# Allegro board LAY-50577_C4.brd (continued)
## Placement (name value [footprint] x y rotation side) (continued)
NOREF#382  -  []  43.78 72.53 90 top
NOREF#383  -  []  133.83 41.2 0 top
NOREF#384  -  []  25.45 88.8 0 top
NOREF#385  -  []  83.29 7.45 90 top
NOREF#386  -  []  130.23 108.22 90 top
NOREF#387  -  []  110.98 104.71 90 top
NOREF#388  -  []  83.87 128.98 90 top
NOREF#389  -  []  106.8 104.59 90 top
NOREF#390  -  []  103.8 117.48 0 top
NOREF#391  -  []  107.3 28.4 0 top
NOREF#392  -  []  17.47 6.14 0 top
NOREF#393  -  []  151.28 118.2 90 top
NOREF#394  -  []  44.06 79.82 0 top
NOREF#395  -  []  73.37 129.71 0 top
NOREF#396  -  []  60.01 28.57 0 top
NOREF#397  -  []  43.57 6.99 90 top
NOREF#398  -  []  132.14 116.34 90 top
NOREF#399  -  []  94.12 136.35 0 top
NOREF#400  -  []  44.06 83.51 0 top
NOREF#401  -  []  184.84 57.38 0 top
NOREF#402  -  []  42.13 84.28 0 top
NOREF#403  -  []  69.83 10.49 0 top
NOREF#404  -  []  101.03 70.84 0 top
NOREF#405  -  []  136.07 94.51 90 top
NOREF#406  -  []  27.95 62.56 0 top
NOREF#407  -  []  0.36 129.9 0 top
NOREF#408  -  []  42.13 80.6 0 top
NOREF#409  -  []  104.95 117.48 90 top
NOREF#410  -  []  44.06 76.14 0 top
NOREF#411  -  []  111.68 105.37 90 top
NOREF#412  -  []  24.27 60.15 0 top
NOREF#413  -  []  6.73 13.77 90 top
NOREF#414  -  []  149.85 122.51 90 top
NOREF#415  -  []  39.15 113.38 90 top
NOREF#416  -  []  145.53 122.78 90 top
NOREF#417  -  []  123.1 24.13 0 top
NOREF#418  -  []  102.89 68.87 0 top
NOREF#419  -  []  10.89 99.12 0 top
NOREF#420  -  []  32.65 88.09 0 top
NOREF#421  -  []  82.02 16.34 0 top
NOREF#422  -  []  165.05 112.24 90 top
NOREF#423  -  []  191.46 87.67 90 top
NOREF#424  -  []  139.21 122.2 90 top
NOREF#425  -  []  102.08 71.17 90 top
NOREF#426  -  []  17.25 135.97 0 top
NOREF#427  -  []  167.23 36.07 0 top
NOREF#428  -  []  108.58 45.09 90 top
NOREF#429  -  []  42.78 73.94 0 top
NOREF#430  -  []  118.26 90.02 0 top
NOREF#431  -  []  155.96 123.13 90 top
NOREF#432  -  []  170.76 96.92 0 top
NOREF#433  -  []  30.3 1.64 90 top
NOREF#434  -  []  27.7 57.74 0 top
NOREF#435  -  []  6.47 119.99 90 top
NOREF#436  -  []  85.14 122.69 90 top
NOREF#437  -  [unnamed#2]  191.07 9.43 0 top
NOREF#438  -  []  10.89 99.12 90 top
NOREF#439  -  []  95.92 58.1 90 top
NOREF#440  -  []  185.48 56.28 0 top
NOREF#441  -  []  154.54 73.43 0 top
NOREF#442  -  []  151.23 122.78 90 top
NOREF#443  -  []  59.2 84.28 0 top
NOREF#444  -  []  50.27 13.8 90 top
NOREF#445  -  []  162.03 59.26 0 top
NOREF#446  -  []  70.12 136.35 0 top
NOREF#447  -  []  145.64 72.02 90 top
NOREF#448  -  []  50.63 3.37 0 top
NOREF#449  -  []  42.13 65.86 0 top
NOREF#450  -  []  91.76 28.57 90 top
NOREF#451  -  []  15.89 107.65 0 top
NOREF#452  -  []  110.2 104.59 0 top
NOREF#453  -  []  101.12 71.46 90 top
NOREF#454  -  []  32.31 82.43 90 top
NOREF#455  -  []  134.92 94.51 0 top
NOREF#456  -  []  119.37 135.23 90 top
NOREF#457  -  []  154.3 123.95 0 top
NOREF#458  -  []  43.78 83.57 90 top
NOREF#459  -  []  100.93 71.17 0 top
NOREF#460  -  [unnamed#2]  3.41 130.95 180 bottom
NOREF#461  -  [unnamed#2]  9.12 4.65 180 bottom
NOREF#462  -  []  186.67 67.13 180 bottom
NOREF#463  -  [unnamed#2]  191.07 9.43 180 bottom
NOREF#464  -  [unnamed#2]  185.1 136.16 180 bottom
NOREF#465  -  []  186.67 60.02 180 bottom
NOREF#466  -  []  105.64 1.09 180 bottom
NOREF#467  -  []  168.76 25.61 180 bottom
P2  POM-2244P-C3310-2-R  [MIC_WM-63PR]  98.53 121.24 0 top
Q1  FDMA530PZ  [MLP6_2X2MM_SLUG]  25.76 12.27 180 top
Q2  FDMA530PZ  [MLP6_2X2MM_SLUG]  28.05 16.84 0 top
Q3  MMBT3906TT1G  [SC_75]  21.19 15.06 0 top
Q4  BSH111BK  [SOT23_A]  18.9 20.91 0 top
Q5  2SK3018  [SOT323_3]  140.06 100.79 270 top
Q6  IRLML6401  [SOT-23]  141.46 134.32 180 bottom
Q7  BC817-40LT1G  [SOT23]  120.38 35.13 270 top
Q8  BC817-40LT1G  [SOT23]  120.38 38.81 270 top
Q11  2SK3018  [SOT323_3]  181.97 53.04 0 top
Q12  2SK3018  [SOT323_3]  184.89 69.42 0 top
Q15  BSS138  [SOT23_A]  37.57 119.08 270 top
Q19  BC817-40LT1G  [SOT23]  113.9 123.42 270 bottom
Q20  BC817-40LT1G  [SOT23]  113.9 119.84 270 bottom
Q21  BC817-40LT1G  [SOT23]  113.9 116.23 270 bottom
Q23  BC817-40LT1G  [SOT23]  113.9 112.65 270 bottom
R1  0  [0402_CC]  22.46 12.6 90 top
R2  0  [0402_CC]  23.48 12.6 90 top
R3  3.3K  [0402_CC]  18.01 14.81 90 top
R4  100K  [0402_CC]  23.98 15.83 90 top
R5  10K  [0402_CC]  18.9 14.81 270 top
R6  1K  [0402_CC]  12.81 20.02 90 top
R7  1K  [0402_CC]  13.19 25.1 180 top
R8  2.2K  [0402_CC]  10.65 24.72 90 top
R9  3.3K  [0402_CC]  10.65 26.62 90 top
R10  10K  [0402_CC]  19.54 17.35 180 top
R11  100K  [0402_CC]  19.54 18.37 0 top
R12  0  [RC0603_OV]  31.6 28.91 180 top
R13  100K  [0402_CC]  18.14 29.42 90 top
R14  180K  [0402_CC]  20.17 30.94 270 top
R15  10K  [0402_CC]  19.16 29.42 270 top
R16  40.2K  [0402_CC]  19.16 30.94 90 top
R17  0  [0402_CC]  17 30.18 270 top
R18  100  [0402_CC]  11.41 36.78 270 top
R19  1M  [0402_CC]  14.08 36.78 90 top
R20  0  [0402_CC]  125.71 59.51 90 top
R21  464K  [0402_CC]  109.33 42.37 270 top
R22  0  [0402_CC]  127.62 40.34 90 top
R23  200K  [0402_CC]  110.6 41.99 0 top
R24  464K  [0402_CC]  136.12 97.36 0 top
R25  243K  [0402_CC]  134.35 97.36 180 top
R26  0.02  [RC0603_OV]  138.91 134.7 90 bottom
R27  200K  [0402_CC]  136.12 98.63 180 top
R28  100K  [0402_CC]  137.65 100.79 270 top
R29  0  [0402_CC]  142.09 130.51 0 bottom
R30  10K  [0402_CC]  142.09 131.52 180 bottom
R31  100K  [0402_CC]  30.33 8.21 270 top
R32  220  [RC0603_OV]  123.93 34.37 0 top
R33  220  [RC0603_OV]  123.93 37.29 0 top
R34  100K  [0402_CC]  10.14 36.78 90 top
R35  2.20K  [RC0603_OV]  115.42 36.15 180 top
R36  2.20K  [RC0603_OV]  115.42 39.83 180 top
R37  100K  [0402_CC]  26.27 8.21 270 top
R38  22K  [0402_CC]  117.58 35.77 270 top
R39  22K  [0402_CC]  117.58 39.45 270 top
R40  0  [0402_CC]  112.12 44.91 90 top
R41  0.005  [RC0603_OV]  111.11 51.13 90 top
R42  100K  [0402_CC]  99.93 48.72 90 top
R43  0  [0402_CC]  111.36 46.94 270 top
R44  100K  [0402_CC]  99.35 49.74 90 bottom
R45  1K  [0402_CC]  116.19 47.2 90 top
R47  0  [0402_CC]  102.98 58.09 270 bottom
R51  0  [0402_CC]  118.73 47.2 90 top
R52  0.005  [RC0603_OV]  121.14 51.13 90 top
R53  4.7K  [0402_CC]  85.07 62.31 270 top
R54  0.005  [RC0603_OV]  79.1 47.7 90 top
R55  4.7K  [0402_CC]  87.1 62.31 90 top
R56  30K  [0402_CC]  85.07 64.47 90 bottom
R57  0  [0402_CC]  87.1 64.47 270 bottom
R58  0.005  [RC0603_OV]  106.03 51.13 90 top
R59  0.005  [RC0603_OV]  86.4 47.7 90 top
R62  1M  [0402_CC]  109.45 58.37 0 top
R64  10K  [0402_CC]  107.8 83.01 270 bottom
R65  10K  [0402_CC]  109.71 83.01 270 bottom
R71  0  [0402_CC]  106.91 83.01 270 bottom
R74  0  [0402_CC]  92.82 90.88 90 top
R76  0  [0402_CC]  96.88 90.88 90 top
R79  0  [0402_CC]  94.85 90.88 90 top
R80  0  [0402_CC]  93.83 90.88 90 top
R81  0  [0402_CC]  91.8 90.88 90 bottom
R82  0  [0402_CC]  90.79 90.88 90 top
R83  0  [0402_CC]  89.01 92.66 90 top
R84  0  [0402_CC]  87.36 92.66 90 top
R85  0  [0402_CC]  85.83 92.66 90 top
R86  0  [0402_CC]  85.07 90.88 90 top
R87  0  [0402_CC]  84.18 92.66 90 top
R88  0  [0402_CC]  88.25 90.88 90 top
R89  0  [0402_CC]  86.59 90.88 90 top
R92  0  [0402_CC]  89.01 92.66 90 bottom
R93  0  [0402_CC]  87.36 92.66 90 bottom
R94  0  [0402_CC]  85.83 92.66 90 bottom
R95  0  [0402_CC]  85.07 90.88 90 bottom
R96  0  [0402_CC]  83.17 92.66 90 bottom
R97  0  [0402_CC]  84.18 92.66 90 bottom
R98  0  [0402_CC]  88.25 90.88 90 bottom
R99  0  [0402_CC]  86.59 90.88 90 bottom
R100  0  [0402_CC]  145.78 83.77 90 top
R101  0  [0402_CC]  154.92 83.77 90 top
R102  0  [0402_CC]  142.73 64.85 90 top
R103  0  [0402_CC]  132.57 57.86 90 top
R104  0  [0402_CC]  142.22 63.07 270 top
R105  0  [0402_CC]  148.37 46.36 180 top
R106  0  [0402_CC]  142.73 51.89 0 top
R107  0  [0402_CC]  137.14 55.07 0 top
R108  0  [0402_CC]  140.82 57.48 270 top
R109  0  [0402_CC]  141.2 59.51 90 top
R110  0  [0402_CC]  136.89 66.12 270 top
R111  0  [0402_CC]  99.93 90.88 270 top
R112  0  [0402_CC]  125.08 68.66 90 top
R113  0  [0402_CC]  136.38 61.8 90 top
R114  0  [0402_CC]  102.47 89.49 180 bottom
R115  0  [0402_CC]  101.58 90.88 90 top
R116  0  [0402_CC]  131.81 61.8 90 top
R117  0  [0402_CC]  107.04 98.25 90 top
R118  0  [0402_CC]  132.19 63.96 90 top
R119  0  [0402_CC]  105.01 98.25 90 top
R120  0  [0402_CC]  129.39 68.66 90 top
R121  0  [0402_CC]  109.07 98.25 90 top
R122  0  [0402_CC]  128 68.91 0 top
R123  0  [0402_CC]  102.98 98.25 90 top
R124  0  [0402_CC]  130.41 70.31 270 top
R125  0  [0402_CC]  99.8 90.88 90 bottom
R126  0  [0402_CC]  133.08 70.56 270 top
R127  0  [0402_CC]  102.09 90.88 90 bottom
R128  0  [0402_CC]  131.3 70.31 270 top
R129  0  [0402_CC]  100.82 90.88 90 bottom
R130  0  [0402_CC]  132.7 72.09 90 top
R131  0  [0402_CC]  106.03 97.11 180 bottom
R132  0  [0402_CC]  103.99 97.11 180 bottom
R133  0  [0402_CC]  109.33 97.11 180 bottom
R134  0  [0402_CC]  101.96 97.11 180 bottom
R135  0  [0402_CC]  150.91 46.74 270 top
R136  0  [0402_CC]  136.89 58.42 180 top
R137  0  [0402_CC]  140.32 59.51 90 top
R138  0  [0402_CC]  125.08 67.64 180 bottom
R139  0  [0402_CC]  126.09 68.66 90 top
R140  0  [0402_CC]  135.49 61.8 90 top
R141  0  [0402_CC]  133.58 61.8 90 top
R142  0  [0402_CC]  130.41 63.96 90 top
R143  0  [0402_CC]  130.66 68.28 0 top
R144  0  [0402_CC]  132.19 70.31 270 top
R146  0  [0402_CC]  133.97 70.56 270 top
R148  0  [0402_CC]  134.35 68.48 90 top
R149  0  [0402_CC]  133.58 72.09 90 top
R151  0  [0402_CC]  72.93 84 90 top
R152  0  [0402_CC]  76.05 82.68 90 top
R153  0  [0402_CC]  74.81 81.1 0 top
R154  0  [0402_CC]  77.2 81.36 0 top
R155  0  [0402_CC]  72.5 80.09 180 top
R156  0  [0402_CC]  77.83 80.34 0 top
R157  0  [0402_CC]  72.5 79.07 180 top
R158  0  [0402_CC]  74.91 78.56 180 top
R159  0  [0402_CC]  72.5 78.06 180 top
R160  0  [0402_CC]  68.43 65.86 180 top
R161  0  [0402_CC]  68.43 66.75 180 top
R162  0  [0402_CC]  64.88 69.7 180 top
R163  0  [0402_CC]  64.88 68.71 180 top
R164  0  [0402_CC]  64.88 62.56 180 top
R165  0  [0402_CC]  64.88 66.75 180 top
R166  0  [0402_CC]  68.43 67.64 180 top
R167  0  [0402_CC]  61.83 69.42 180 top
R168  0  [0402_CC]  61.83 64.98 180 top
R169  0  [0402_CC]  64.88 63.58 180 top
R170  0  [0402_CC]  61.83 66.42 180 top
R171  0  [0402_CC]  61.83 61.55 180 top
R172  0  [0402_CC]  61.83 62.56 180 top
R173  0  [0402_CC]  64.88 61.55 180 top
R174  0  [0402_CC]  64.88 64.39 180 top
R175  0  [0402_CC]  69.5 70.16 180 top
R176  0  [0402_CC]  67.16 69.8 180 top
R177  0  [0402_CC]  72.75 76.66 180 top
R178  0  [0402_CC]  74.91 76.15 180 top
R179  0  [0402_CC]  72.75 75.64 180 top
R180  0  [0402_CC]  77.12 75.14 0 top
R181  0  [0402_CC]  74.83 74.63 0 top
R182  0  [0402_CC]  77.17 74.12 0 top
R183  0  [0402_CC]  73.67 72.04 270 top
R184  0  [0402_CC]  75.7 72.09 270 top
R185  0  [0402_CC]  74.91 77.17 180 top
R186  0  [0402_CC]  83.04 63.96 180 bottom
R187  0  [0402_CC]  81.77 63.83 270 top
R188  0  [0402_CC]  82.96 60.91 0 top
R189  0  [0402_CC]  76.05 57.36 90 top
R190  0  [0402_CC]  72.5 55.7 180 top
R191  0  [0402_CC]  74.91 55.2 180 top
R192  0  [0402_CC]  72.5 54.43 180 top
R193  0  [0402_CC]  72.37 53.04 180 top
R194  0  [0402_CC]  74.78 52.53 180 top
R195  0  [0402_CC]  72.37 52.02 180 top
R196  0  [0402_CC]  74.78 51.51 180 top
R198  0  [0402_CC]  72.37 51.01 180 top
R200  0  [0402_CC]  74.78 50.5 180 top
R201  0  [0402_CC]  72.37 49.99 180 top
R202  0  [0402_CC]  74.78 49.48 180 top
R203  0  [0402_CC]  72.5 82.25 180 bottom
R204  0  [0402_CC]  74.78 53.55 180 top
R205  0  [0402_CC]  74.91 81.61 180 bottom
R206  0  [0402_CC]  72.5 81.1 180 bottom
R207  0  [0402_CC]  74.91 80.6 180 bottom
R208  0  [0402_CC]  72.5 80.09 180 bottom
R209  0  [0402_CC]  74.91 79.58 180 bottom
R210  0  [0402_CC]  72.5 79.07 180 bottom
R211  0  [0402_CC]  74.91 78.56 180 bottom
R212  0  [0402_CC]  72.5 78.06 180 bottom
R213  0  [0402_CC]  70.21 66.88 90 bottom
R214  0  [0402_CC]  68.31 66.75 180 bottom
R215  0  [0402_CC]  64.88 69.7 180 bottom
R216  0  [0402_CC]  64.88 67.9 180 bottom
R217  0  [0402_CC]  64.88 62.82 180 bottom
R218  0  [0402_CC]  64.88 66.75 180 bottom
R219  0  [0402_CC]  61.83 65.23 180 bottom
R220  0  [0402_CC]  64.88 63.71 180 bottom
R221  0  [0402_CC]  61.83 66.63 180 bottom
R222  0  [0402_CC]  61.83 61.42 180 bottom
R223  0  [0402_CC]  61.83 62.31 180 bottom
R224  0  [0402_CC]  64.88 61.42 180 bottom
R225  0  [0402_CC]  67.42 62.29 270 bottom
R226  0  [0402_CC]  70.59 69.17 270 bottom
R227  0  [0402_CC]  69.45 70.06 0 bottom
R228  0  [0402_CC]  74.91 56.21 180 bottom
R229  0  [0402_CC]  72.5 55.7 180 bottom
R230  0  [0402_CC]  74.91 55.2 180 bottom
R231  0  [0402_CC]  72.5 54.69 180 bottom
R232  0  [0402_CC]  76.56 51.51 270 bottom
R233  0  [0402_CC]  77.45 51.51 270 bottom
R234  0  [0402_CC]  72.37 52.02 180 bottom
R235  0  [0402_CC]  74.78 51.51 180 bottom
R238  0  [0402_CC]  77.58 48.34 270 bottom
R240  0  [0402_CC]  76.56 48.34 270 bottom
R242  0  [0402_CC]  73.64 48.47 270 bottom
R244  0  [0402_CC]  75.16 48.47 270 bottom
R246  0  [0402_CC]  77.83 53.04 0 bottom
R248  0  [0402_CC]  96.5 49.74 270 bottom
R250  0  [0402_CC]  98 53.85 90 bottom
R252  0  [0402_CC]  97.39 49.74 270 bottom
R256  10K  [0402_CC]  150.73 120.47 90 top
R257  0  [0402_CC]  149.84 120.47 270 top
R258  0  [0402_CC]  147.43 119.97 0 bottom
R259  10K  [0402_CC]  151.62 120.47 270 top
R260  100K  [0402_CC]  145.78 131.14 0 bottom
R264  33K  [0402_CC]  151.49 65.99 0 top
R266  33K  [0402_CC]  150.6 67.9 180 top
R270  10K  [0402_CC]  148.32 65.43 180 top
R271  0  [RC0402_25]  115.55 15.06 90 top
R272  0  [RC0402_25]  116.57 15.06 90 top
R273  0  [RC0402_25]  117.58 15.06 90 top
R274  0  [RC0402_25]  118.6 15.06 90 top
R275  0  [RC0402_25]  119.61 15.06 90 top
R276  0  [RC0402_25]  120.63 15.06 90 top
R277  0  [RC0402_25]  121.52 15.06 90 top
R280  0  [RC0402_25]  122.28 2.49 90 top
R283  0  [RC0402_25]  124.95 2.49 90 top
R284  0  [RC0402_25]  126.09 2.49 90 top
R285  0  [RC0402_25]  126.6 15.06 90 top
R287  10K  [0402_CC]  101.96 113.62 0 bottom
R288  10K  [0402_CC]  104.5 109.04 90 bottom
R289  10K  [0402_CC]  100.69 112.09 270 bottom
R290  10K  [0402_CC]  107.3 124.03 90 top
R291  33K  [0402_CC]  105.01 123.14 180 top
R292  33K  [0402_CC]  107.17 121.49 90 top
R293  0  [0402_CC]  101.96 114.51 0 bottom
R294  10K  [0402_CC]  101.96 117.17 180 bottom
R295  47K  [RC0402_25]  131.93 15.06 90 top
R296  0  [0402_CC]  101.43 109.17 0 bottom
R297  0  [0402_CC]  103.36 110.37 90 bottom
R298  0  [0402_CC]  100.06 101.68 180 top
R299  0  [0402_CC]  101.96 116.28 0 bottom
R303  0  [0402_CC]  101.96 111.71 0 bottom
R308  0  [0402_CC]  101.96 112.73 0 bottom
R312  0  [0402_CC]  101.58 110.44 90 bottom
R313  10K  [0402_CC]  68.18 95.33 0 top
R314  0  [0402_CC]  68.18 94.31 0 top
R315  0  [0402_CC]  68.18 93.04 0 top
R316  10K  [0402_CC]  80.24 93.04 180 top
R317  10K  [0402_CC]  68.18 91.77 0 top
R318  0  [0402_CC]  80.24 91.77 180 top
R319  0  [0402_CC]  80.24 90.5 180 top
R320  4.7K  [0402_CC]  57.38 79.33 180 bottom
R327  0  [0402_CC]  57.77 72.21 90 bottom
R331  100K  [0402_CC]  58.78 75.77 90 bottom
R332  0  [0402_CC]  87.48 82.5 180 bottom
R333  0  [0402_CC]  85.96 84.03 180 bottom
R335  10K  [0402_CC]  86.59 80.98 90 bottom
R336  4.7K  [0402_CC]  56.75 51.77 90 bottom
R337  0  [0402_CC]  57.77 51.77 270 bottom
R338  100K  [0402_CC]  58.65 51.77 270 bottom
R339  0  [0402_CC]  152.38 51.39 0 top
R341  0  [0402_CC]  152.38 50.5 0 top
R343  0  [0402_CC]  157.71 49.74 0 bottom
R344  0  [0402_CC]  116.19 86.82 180 bottom
R348  0  [0402_CC]  187.05 86.82 180 top
R350  0  [0402_CC]  154.67 121.36 0 top
R375  10K  [0402_CC]  131.93 20.65 180 bottom
R376  100  [0402_CC]  134.85 20.02 180 bottom
R377  75.0  [RC0805_OV]  139.68 21.8 0 bottom
R378  10K  [0402_CC]  130.92 19.38 270 top
R379  374  [RC0805_OV]  149.33 20.02 0 bottom
R380  93.1  [RC0603_OV]  153.9 21.8 0 bottom
R381  0  [0402_CC]  146.28 20.65 0 bottom
R382  0  [0402_CC]  155.94 23.45 90 bottom
R391  49.9  [RC0603_OV]  53.5 25.35 0 top
R392  49.9  [RC0603_OV]  56.17 25.35 180 top
R393  49.9  [RC0603_OV]  58.83 25.35 0 top
R395  49.9  [RC0603_OV]  61.5 25.35 180 top
R396  1.5K  [0402_CC]  53.83 36.78 270 top
R397  1K  [0402_CC]  54.84 36.78 270 top
R404  100  [0402_CC]  64.62 13.41 270 top
R405  0  [0402_CC]  56.88 36.78 270 top
R408  10K  [0402_CC]  55.99 36.78 90 bottom
R428  4.7K  [0402_CC]  125.2 107.77 270 bottom
R429  4.7K  [0402_CC]  126.09 107.77 270 bottom
R430  4.7K  [0402_CC]  123.42 107.77 270 bottom
R431  4.7K  [0402_CC]  127.87 107.77 270 bottom
R432  4.7K  [0402_CC]  126.98 105.23 270 bottom
R433  4.7K  [0402_CC]  124.31 107.77 270 bottom
R434  4.7K  [0402_CC]  132.95 106.63 180 top
R435  4.7K  [0402_CC]  132.95 109.43 180 top
R436  4.7K  [0402_CC]  132.95 110.31 180 top
R437  4.7K  [0402_CC]  132.95 107.52 0 top
R438  4.7K  [0402_CC]  132.95 108.54 0 top
R439  4.7K  [0402_CC]  132.95 111.2 0 top
R440  4.7K  [0402_CC]  125.2 105.23 270 bottom
R441  4.7K  [0402_CC]  126.09 105.23 270 bottom
R442  4.7K  [0402_CC]  123.42 105.23 270 bottom
R443  4.7K  [0402_CC]  127.87 105.23 270 bottom
R444  4.7K  [0402_CC]  126.98 107.77 270 bottom
R445  4.7K  [0402_CC]  124.31 105.23 270 bottom
R446  4.7K  [0402_CC]  115.68 102.69 90 top
R447  1.5K  [0402_CC]  120.25 113.49 0 top
R448  0  [0402_CC]  116.57 102.69 90 top
R449  510  [0402_CC]  116.44 134.95 180 top
R450  4.7K  [0402_CC]  116.19 108.92 270 bottom
R451  4.7K  [0402_CC]  120.25 114.51 0 top
R452  510  [0402_CC]  136.63 135.84 270 top
R453  0  [0402_CC]  116.19 106.63 90 bottom
R454  100  [0402_CC]  136.63 132.03 270 top
R455  0  [0402_CC]  130.79 109.04 0 bottom
R456  0  [0402_CC]  131.68 116.92 90 top
R457  0  [0402_CC]  129.9 107.77 270 bottom
R458  0  [0402_CC]  126.09 105.23 270 top
R459  0  [0402_CC]  124.31 105.23 270 top
R460  0  [0402_CC]  125.2 105.23 270 top
R461  0  [0402_CC]  123.42 105.23 270 top
R462  0  [0402_CC]  127.87 105.23 270 top
R463  0  [0402_CC]  126.98 105.23 270 top
R464  4.7K  [0402_CC]  130.54 105.23 270 top
R465  0  [0402_CC]  129.65 105.23 270 top
R466  26.1  [0402_CC]  132.31 112.09 0 top
R467  2.49K  [0402_CC]  132.57 116.92 90 top
R468  0  [RC0603_OV]  127.11 110.57 180 bottom
R469  4.7K  [0402_CC]  122.28 115.39 270 top
R470  0  [RC0603_OV]  130.92 111.97 90 bottom
R472  4.7K  [0402_CC]  31.98 57.74 0 bottom
R473  4.7K  [0402_CC]  31.98 58.63 0 bottom
R474  4.7K  [0402_CC]  31.98 55.96 0 bottom
R475  4.7K  [0402_CC]  31.98 60.4 0 bottom
R476  4.7K  [0402_CC]  31.98 59.51 0 bottom
R477  4.7K  [0402_CC]  31.98 56.85 0 bottom
R479  4.7K  [0402_CC]  33 65.74 270 top
R480  4.7K  [0402_CC]  30.33 65.74 270 top
R481  4.7K  [0402_CC]  29.44 65.74 270 top
R492  4.7K  [0402_CC]  32.11 65.74 90 top
R493  4.7K  [0402_CC]  31.22 65.74 90 top
R494  4.7K  [0402_CC]  28.56 65.74 90 top
R495  4.7K  [0402_CC]  34.52 57.74 0 bottom
R496  4.7K  [0402_CC]  34.52 58.63 0 bottom
R497  4.7K  [0402_CC]  34.52 55.96 0 bottom
R498  4.7K  [0402_CC]  34.52 60.4 0 bottom
R499  4.7K  [0402_CC]  34.52 59.51 0 bottom
R500  4.7K  [0402_CC]  34.52 56.85 0 bottom
R501  1.5K  [0402_CC]  26.4 52.66 90 top
R502  0  [0402_CC]  27.29 52.66 90 top
R503  4.7K  [0402_CC]  25.38 52.66 90 top
R504  0  [0402_CC]  24.49 52.66 90 top
R505  510  [0402_CC]  4.3 49.1 180 top
R506  510  [0402_CC]  3.92 69.17 0 top
R507  100  [0402_CC]  7.73 49.1 0 top
R508  0  [0402_CC]  31.98 63.96 0 bottom
R509  0  [0402_CC]  22.84 64.21 180 top
R510  0  [0402_CC]  33.25 62.18 0 bottom
R511  0  [0402_CC]  34.52 57.74 0 top
R512  0  [0402_CC]  34.52 56.85 0 top
R513  0  [0402_CC]  34.52 55.96 0 top
R514  0  [0402_CC]  34.52 58.63 0 top
R515  0  [0402_CC]  34.52 60.4 0 top
R516  0  [0402_CC]  34.52 59.51 0 top
R517  4.7K  [0402_CC]  34.52 63.07 0 top
R518  0  [0402_CC]  34.52 62.18 0 top
R519  26.1  [0402_CC]  27.67 65.74 90 top
R520  2.49K  [0402_CC]  22.84 65.23 180 top
R521  0  [RC0603_OV]  28.68 59.77 270 bottom
R522  4.7K  [0402_CC]  24.36 54.82 0 top
R523  0  [RC0603_OV]  28.17 63.96 180 bottom
R524  4.7K  [0402_CC]  34.02 83.01 0 bottom
R525  4.7K  [0402_CC]  34.02 83.9 0 bottom
R526  4.7K  [0402_CC]  34.02 81.23 0 bottom
R527  4.7K  [0402_CC]  34.02 85.68 0 bottom
R528  4.7K  [0402_CC]  36.56 84.79 0 bottom
R529  4.7K  [0402_CC]  34.02 82.12 0 bottom
R530  4.7K  [0402_CC]  35.03 91.01 270 top
R531  4.7K  [0402_CC]  32.37 91.01 270 top
R532  4.7K  [0402_CC]  31.48 91.01 270 top
R543  4.7K  [0402_CC]  34.14 91.01 90 top
R544  4.7K  [0402_CC]  33.25 91.01 90 top
R545  4.7K  [0402_CC]  30.59 91.01 90 top
R547  4.7K  [0402_CC]  36.56 83.01 0 bottom
R548  4.7K  [0402_CC]  36.56 83.9 0 bottom
R549  4.7K  [0402_CC]  36.56 81.23 0 bottom
R550  4.7K  [0402_CC]  36.56 85.68 0 bottom
R551  4.7K  [0402_CC]  34.02 84.79 0 bottom
R552  4.7K  [0402_CC]  36.56 82.12 0 bottom
R554  1.5K  [0402_CC]  28.43 77.93 90 top
R555  0  [0402_CC]  29.32 77.93 90 top
R556  4.7K  [0402_CC]  27.41 77.93 90 top
R557  0  [0402_CC]  26.52 77.93 90 top
R558  510  [0402_CC]  4.3 74.5 180 top
R559  510  [0402_CC]  3.92 94.57 0 top
R560  100  [0402_CC]  7.73 94.57 0 top
R561  0  [0402_CC]  34.02 89.11 0 bottom
R562  0  [0402_CC]  24.87 89.49 180 top
R563  0  [0402_CC]  35.29 87.45 0 bottom
R564  0  [0402_CC]  36.56 83.9 0 top
R565  0  [0402_CC]  36.56 81.23 0 top
R566  0  [0402_CC]  36.56 83.01 0 top
R567  0  [0402_CC]  36.56 82.12 0 top
R568  0  [0402_CC]  36.56 85.68 0 top
R569  0  [0402_CC]  36.56 84.79 0 top
R570  4.7K  [0402_CC]  36.56 88.34 0 top
R571  0  [0402_CC]  36.56 87.45 0 top
R572  26.1  [0402_CC]  29.7 91.01 90 top
R573  2.49K  [0402_CC]  24.87 90.5 180 top
R574  0  [RC0603_OV]  31.1 84.74 270 bottom
R575  4.7K  [0402_CC]  26.4 80.09 0 top
R576  0  [RC0603_OV]  30.08 88.85 180 bottom
R622  0  [0402_CC]  186.42 53.67 90 top
R623  0  [0402_CC]  186.54 66.63 180 top
R624  100K  [0402_CC]  181.59 58.12 0 top
R625  0  [0402_CC]  181.59 59.01 0 top
R626  100K  [0402_CC]  183.24 59.39 90 top
R627  100K  [0402_CC]  181.59 57.23 0 top
R628  0  [0402_CC]  186.54 65.61 180 top
R629  10K  [0402_CC]  180.19 53.04 270 top
R630  0  [0402_CC]  181.59 56.34 0 top
R631  10K  [0402_CC]  181.59 55.45 180 top
R632  0  [0402_CC]  188.96 63.07 90 top
R633  0  [0402_CC]  189.34 70.06 90 top
R634  0  [0402_CC]  185.65 78.06 180 top
R635  100K  [0402_CC]  184.51 74.5 0 top
R636  0  [0402_CC]  184.51 75.39 0 top
R637  0  [0402_CC]  185.65 77.04 180 top
R638  100K  [0402_CC]  186.16 75.77 90 top
R639  100K  [0402_CC]  184.51 73.61 0 top
R640  10K  [0402_CC]  183.11 69.42 270 top
R641  0  [0402_CC]  184.51 72.72 0 top
R642  10K  [0402_CC]  184.51 71.83 180 top
R643  0  [0402_CC]  188.96 81.99 90 top
R644  0  [0402_CC]  68.18 102.31 0 top
R646  10K  [0402_CC]  77.96 101.55 180 top
R647  0  [0402_CC]  77.96 100.66 180 top
R648  100K  [0402_CC]  77.96 102.95 0 top
R649  0  [0402_CC]  70.85 114.42 90 top
R650  62  [RC0805_OV]  72.06 118.49 0 top
R651  62  [RC0805_OV]  68.6 118.49 0 top
R652  0  [0402_CC]  69.83 114.42 90 top
R653  0  [0402_CC]  68.18 108.03 0 top
R655  10K  [0402_CC]  77.96 106.89 180 top
R656  0  [0402_CC]  77.96 107.77 180 top
R657  100K  [0402_CC]  77.96 108.66 0 top
R658  0  [0402_CC]  77.58 114.42 90 top
R659  62  [RC0805_OV]  78.79 118.49 0 top
R660  62  [RC0805_OV]  75.33 118.49 0 top
R661  0  [0402_CC]  76.56 114.42 90 top
R662  10K  [0402_CC]  169.78 125.55 180 top
R663  27  [0402_CC]  167.87 126.44 180 top
R664  0  [0402_CC]  169.78 126.44 180 top
R665  10K  [0402_CC]  169.78 123.78 180 top
R666  1.00k  [0402_CC]  171.05 107.39 180 top
R667  1.00k  [0402_CC]  169.02 107.39 0 top
R668  0  [0402_CC]  154.41 114 0 top
R669  0  [0402_CC]  169.78 124.67 180 top
R670  0  [0402_CC]  154.41 114.89 0 top
R671  0  [0402_CC]  154.41 115.78 0 top
R672  0  [0402_CC]  154.41 116.66 0 top
R673  0  [0402_CC]  154.41 117.55 0 top
R674  0  [0402_CC]  154.41 118.44 0 top
R675  0  [0402_CC]  157.46 105.74 90 top
R676  0  [0402_CC]  162.79 105.74 90 top
R677  0  [0402_CC]  167.87 116.54 180 top
R678  0  [0402_CC]  167.87 117.43 180 top
R679  27  [0402_CC]  167.87 123.78 180 top
R680  0  [0402_CC]  167.87 118.32 180 top
R681  0  [0402_CC]  167.87 119.2 180 top
R682  0  [0402_CC]  167.87 120.09 180 top
R683  0  [0402_CC]  167.87 112.98 180 top
R684  0  [0402_CC]  167.87 113.87 180 top
R685  0  [0402_CC]  167.87 114.76 180 top
R686  0  [0402_CC]  171.56 122.13 90 top
R687  0  [0402_CC]  167.87 115.65 180 top
R688  0  [0402_CC]  167.87 127.33 180 top
R689  0  [0402_CC]  167.87 128.35 180 top
R690  0  [0402_CC]  184.89 77.04 0 bottom
R691  0  [0402_CC]  184.89 77.93 0 bottom
R692  4.7K  [0402_CC]  167.87 127.33 0 bottom
R694  4.7K  [0402_CC]  167.87 128.35 0 bottom
R696  0  [0402_CC]  156.19 95.07 270 top
R697  0  [0402_CC]  155.43 95.07 270 top
R699  0  [0402_CC]  154.67 95.07 270 top
R701  0  [0402_CC]  155.43 105.74 270 top
R703  0  [0402_CC]  154.54 105.74 270 top
R705  0  [0402_CC]  161.02 95.84 0 top
R706  0  [0402_CC]  158.48 105.74 270 top
R707  100K  [0402_CC]  54.34 96.47 90 top
R708  4.7K  [0402_CC]  54.34 96.47 270 bottom
R709  100K  [0402_CC]  53.07 96.47 90 top
R710  4.7K  [0402_CC]  53.07 96.47 270 bottom
R711  100K  [0402_CC]  51.8 96.47 90 top
R712  4.7K  [0402_CC]  51.8 96.47 270 bottom
R713  10K  [0402_CC]  17.25 128.73 90 top
R714  10K  [0402_CC]  21.32 129.11 180 top
R715  10K  [0402_CC]  29.95 128.73 90 top
R716  10K  [0402_CC]  32.49 128.73 90 top
R717  10K  [0402_CC]  35.03 128.73 90 top
R718  100  [0402_CC]  37.57 128.73 90 top
R719  10K  [0402_CC]  27.41 128.73 270 top
R720  10K  [0402_CC]  26.14 128.73 270 top
R721  10K  [0402_CC]  14.71 128.73 270 top
R722  0  [0402_CC]  96.88 90.88 270 bottom
R723  0  [0402_CC]  92.82 90.88 270 bottom
R724  0  [0402_CC]  136.12 68.48 270 top
R725  0  [0402_CC]  138.16 61.8 270 top
R726  0  [0402_CC]  128 68.02 180 top
R727  0  [0402_CC]  140.32 63.07 90 top
R728  5.6K  [0402_CC]  133.71 46.56 90 top
R729  0  [0402_CC]  132.57 56.34 90 top
R730  0  [0402_CC]  139.43 59.51 270 top
R731  0  [0402_CC]  144 64.47 180 top
R732  0  [0402_CC]  138.03 66.5 180 top
R733  0  [0402_CC]  155.94 83.77 270 top
R734  0  [0402_CC]  149.89 46.74 90 top
R735  0  [0402_CC]  135.74 71.83 0 top
R736  0  [0402_CC]  142.73 83.77 270 top
R737  0  [0402_CC]  141.2 52.28 270 top
R738  10.0K  [0402_CC]  134.73 46.56 270 top
R746  100  [0402_CC]  152.81 46.36 270 top
R747  0  [0402_CC]  139.3 63.07 270 top
R748  100  [0402_CC]  155.61 46.74 270 top
R749  0  [0402_CC]  154.47 47.12 0 top
R750  0  [0402_CC]  139.93 57.48 90 top
R751  0  [0402_CC]  108.69 83.01 270 bottom
R752  0  [0402_CC]  136.76 57.23 270 top
R753  100  [0402_CC]  158.15 46.87 270 top
R755  0  [0402_CC]  114.79 82.5 180 bottom
R756  0  [0402_CC]  110.6 83.01 270 bottom
R757  0  [0402_CC]  114.79 81.49 180 bottom
R758  0  [0402_CC]  94.85 90.88 270 bottom
R759  0  [0402_CC]  93.83 90.88 270 bottom
R760  0  [0402_CC]  135.87 57.23 90 top
R761  10.0K  [0402_CC]  165.08 83.77 90 top
R762  5.6K  [0402_CC]  164.06 83.77 270 top
R763  0  [0402_CC]  135.74 70.94 0 top
R764  0  [0402_CC]  163.23 46.87 270 top
R765  10.0K  [0402_CC]  166.1 83.77 90 top
R766  5.6K  [0402_CC]  167.11 83.77 270 top
R767  0  [0402_CC]  135.24 68.48 90 top
R768  10.0  [0402_CC]  170.92 32.46 180 top
R769  10.0  [0402_CC]  170.92 33.73 180 top
R770  0  [0402_CC]  163.68 34.75 180 bottom
R771  0  [0402_CC]  165.97 22.18 90 top
R772  0  [0402_CC]  165.59 25.35 180 top
R773  0  [0402_CC]  167.62 26.24 90 top
R774  4.7K  [0402_CC]  171.18 26.24 270 top
R775  75.0K  [RC0402_25]  172.57 23.45 180 top
R776  75.0K  [RC0402_25]  172.83 21.92 180 top
R777  4.7K  [0402_CC]  172.83 20.91 180 top
R778  1.5K  [RC0402_25]  172.57 24.34 180 top
R779  4.7K  [0402_CC]  170.29 26.24 90 top
R780  0  [0402_CC]  169.4 26.24 270 top
R781  0  [0402_CC]  168.51 26.24 270 top
R782  4.7K  [0402_CC]  151.75 31.83 0 top
R783  4.7K  [0402_CC]  151.75 29.29 0 top
R784  0  [0402_CC]  151.75 30.3 180 top
R785  0  [0402_CC]  151.75 32.84 180 top
R798  4.7K  [0402_CC]  153.14 29.92 90 top
R800  4.7K  [0402_CC]  161.14 17.99 90 top
R801  4.7K  [0402_CC]  153.02 32.46 90 top
R803  4.7K  [0402_CC]  160 17.99 270 top
R804  0  [0402_CC]  160.89 27.76 270 top
R805  1.00k  [0402_CC]  144 133.81 270 bottom
R806  1.00k  [0402_CC]  145.01 133.81 270 bottom
R808  100K  [0402_CC]  7.09 105.11 180 top
R809  100  [0402_CC]  6.33 103.08 180 top
R811  20K  [0402_CC]  22.84 115.9 90 top
R812  33  [0402_CC]  22.46 117.05 0 bottom
R813  33  [0402_CC]  22.46 116.16 0 bottom
R814  10K  [0402_CC]  14.2 98.5 180 top
R815  100K  [0402_CC]  14.2 97.49 0 top
R816  10K  [0402_CC]  14.2 101.55 180 top
R817  15K  [0402_CC]  14.2 100.54 0 top
R818  1K  [0402_CC]  14.2 99.52 180 top
R821  0  [0402_CC]  18.65 108.66 180 top
R822  0  [0402_CC]  27.54 109.04 90 top
R823  0  [0402_CC]  26.52 121.49 90 bottom
R824  0  [0402_CC]  24.36 118.19 180 bottom
R825  0  [0402_CC]  30.21 119.71 0 bottom
R826  0  [0402_CC]  33.25 114.25 0 bottom
R827  0  [0402_CC]  33.25 114.76 0 top
R828  0  [0402_CC]  33.25 115.14 0 bottom
R829  10K  [0402_CC]  39.99 119.59 270 top
R830  10K  [0402_CC]  20.68 121.87 0 top
R831  10  [0402_CC]  44.56 108.16 0 top
R832  10  [0402_CC]  44.56 107.27 0 top
R833  10  [0402_CC]  29.95 106.76 0 top
R834  10  [0402_CC]  34.91 98.25 0 top
R835  10  [0402_CC]  35.03 101.04 0 top
R836  2.0K  [0402_CC]  29.06 104.73 180 top
R837  2.0K  [0402_CC]  35.03 101.93 0 top
R838  2.0K  [0402_CC]  22.08 123.14 270 top
R839  2.0K  [0402_CC]  22.97 123.14 90 top
R840  2.0K  [0402_CC]  37.57 102.69 0 top
R841  10  [0402_CC]  37.57 103.71 0 top
R842  10K  [0402_CC]  41.13 98.63 90 bottom
R844  0  [0402_CC]  28.56 119.71 180 bottom
R845  0  [0402_CC]  26.02 110.7 0 top
R846  0  [0402_CC]  36.94 113.11 180 top
R847  0  [0402_CC]  36.94 114.12 180 top
R848  100  [0402_CC]  43.8 113.11 180 top
R849  10K  [0402_CC]  40.11 117.81 270 top
R850  10K  [0402_CC]  21.57 115.52 0 top
R851  100K  [0402_CC]  34.65 120.7 180 top
R852  0  [0402_CC]  29.57 122.63 90 top
R853  3.3K  [0402_CC]  32.37 108.03 270 top
R854  3.3K  [0402_CC]  34.91 108.03 270 top
R861  10K  [0402_CC]  30.21 118.82 0 bottom
R862  10K  [0402_CC]  33.25 116.03 0 bottom
R863  10K  [0402_CC]  33.25 115.65 0 top
R864  10K  [0402_CC]  33.25 113.36 0 bottom
R865  10K  [0402_CC]  27.54 121.49 90 bottom
R866  10K  [0402_CC]  24.36 119.08 180 bottom
R867  0  [0402_CC]  150.73 83.77 90 top
R868  0  [0402_CC]  153.65 83.77 90 top
R869  0  [0402_CC]  147.81 83.77 90 top
R870  0  [0402_CC]  151.62 83.77 90 top
R871  0  [0402_CC]  144.76 83.77 90 top
R872  0  [0402_CC]  156.95 83.77 90 top
R873  0  [0402_CC]  159.24 83.77 90 top
R874  0  [0402_CC]  161.78 83.77 90 top
R875  2.20K  [RC0603_OV]  116.69 124.54 270 bottom
R876  22K  [0402_CC]  114.53 125.68 180 bottom
R877  220  [RC0603_OV]  114.03 121.87 0 top
R878  2.20K  [RC0603_OV]  117.71 120.09 270 bottom
R879  22K  [0402_CC]  116.44 120.47 270 bottom
R880  220  [RC0603_OV]  114.03 118.32 0 top
R881  0  [0402_CC]  122.66 109.81 270 top
R882  0  [0402_CC]  121.65 109.81 270 top
R883  0  [0402_CC]  120.25 109.93 180 top
R884  0  [0402_CC]  120.25 111.33 180 top
R885  2.20K  [RC0603_OV]  117.71 116.54 270 bottom
R886  22K  [0402_CC]  116.44 116.92 270 bottom
R887  220  [RC0603_OV]  114.03 114.76 0 top
R891  2.20K  [RC0603_OV]  117.71 112.98 270 bottom
R892  22K  [0402_CC]  116.44 113.36 270 bottom
R893  220  [RC0603_OV]  114.03 111.2 0 top
R897  10K  [0402_CC]  59.92 120.86 180 top
R898  1K  [0402_CC]  48.11 128.09 270 top
R899  1K  [0402_CC]  47.1 128.09 270 top
R900  4.7K  [0402_CC]  50.02 128.48 0 top
R901  100K  [0402_CC]  34.91 97.36 180 top
R902  100K  [0402_CC]  35.03 100.15 180 top
R903  100K  [0402_CC]  29.19 105.74 0 top
R904  0  [0402_CC]  141.84 64.85 90 top
R958  0  [0402_CC]  102.98 90.88 90 bottom
R959  0  [0402_CC]  61.83 68.4 180 top
R960  0  [0402_CC]  61.83 68.28 180 bottom
R964  0  [0402_CC]  50.91 26.75 90 top
R1018  0  [0402_CC]  89.01 39.07 270 top
R1021  0  [0402_CC]  187.31 27.89 180 top
R1022  0  [0402_CC]  187.31 25.35 0 top
R1023  0  [0402_CC]  187.31 31.32 0 top
R1024  0  [0402_CC]  187.31 29.92 0 top
R1025  0  [0402_CC]  187.31 28.91 0 top
R1026  4.7K  [0402_CC]  63.86 94.69 0 bottom
R1027  4.7K  [0402_CC]  63.86 95.58 0 bottom
R1028  0  [0402_CC]  63.86 95.58 180 top
R1029  0  [0402_CC]  57 92.66 180 top
R1030  0  [0402_CC]  57 94.44 180 top
R1031  10K  [0402_CC]  63.86 92.92 0 top
R1032  0  [0402_CC]  63.86 94.69 0 top
R1033  10K  [0402_CC]  57 93.55 0 top
R1034  10K  [0402_CC]  57 91.77 180 top
R1035  10K  [0402_CC]  63.86 92.03 0 top
R1036  10K  [0402_CC]  63.86 91.14 180 top
R1038  100K  [0402_CC]  63.86 93.8 180 top
R1039  10K  [0402_CC]  57 92.66 180 bottom
R1040  10K  [0402_CC]  57 94.44 180 bottom
R1041  100K  [0402_CC]  112.76 22.94 90 top
R1042  0  [0402_CC]  133.46 68.48 90 top
R1043  0  [0402_CC]  187.05 88.72 180 top
R1044  0  [0402_CC]  187.05 87.71 180 top
R1045  0  [0402_CC]  116.19 87.71 0 bottom
R1046  0  [0402_CC]  116.19 88.6 0 bottom
R1047  0  [0402_CC]  152.76 125.05 90 bottom
R1048  0  [0402_CC]  152.76 123.4 270 bottom
R1049  0  [0402_CC]  137.78 70.56 270 bottom
R1051  0  [0402_CC]  136.76 70.56 270 bottom
R1052  0  [0402_CC]  114.15 68.91 0 top
R1053  0  [0402_CC]  179.05 53.93 90 top
R1054  0  [0402_CC]  157.97 83.77 270 top
R1055  0  [0402_CC]  179.05 52.28 90 top
R1056  0  [0402_CC]  152.63 83.77 270 top
R1057  0  [0402_CC]  148.37 47.25 0 top
R1058  0  [0402_CC]  137.14 55.96 180 top
R1059  0  [0402_CC]  133.58 57.1 90 top
R1061  0  [0402_CC]  137.27 61.8 270 top
R1062  0  [0402_CC]  131.3 63.96 270 top
R1063  0  [0402_CC]  135.87 66.12 90 top
R1064  0  [0402_CC]  143.74 83.77 90 top
R1065  0  [0402_CC]  139.05 57.48 270 top
R1066  0  [0402_CC]  141.33 63.07 270 top
R1067  0  [0402_CC]  148.82 83.77 90 top
R1068  0  [0402_CC]  139.68 51.89 180 top
R1069  0  [0402_CC]  140.95 64.85 90 top
R1071  0  [0402_CC]  125.33 67.39 0 top
R1072  0  [0402_CC]  132.7 61.8 90 top
R1073  0  [0402_CC]  138.41 59.51 90 top
R1074  0  [0402_CC]  36.94 115.01 180 top
R1075  0  [0402_CC]  36.94 115.9 180 top
R1076  100  [0402_CC]  43.8 114 180 top
R1077  100  [0402_CC]  43.8 114.89 180 top
R1078  100  [0402_CC]  43.8 115.78 180 top
R1079  0  [0402_CC]  95.87 90.88 90 bottom
R1080  0  [0402_CC]  97.39 88.72 180 bottom
R1081  0  [0402_CC]  89.77 90.88 90 top
R1083  0  [0402_CC]  89.77 90.88 90 bottom
R1084  0  [0402_CC]  90.79 90.88 90 bottom
R1085  0  [0402_CC]  97.77 90.88 90 top
R1086  0  [0402_CC]  95.87 90.88 90 top
R1087  0  [0402_CC]  91.8 90.88 90 top
R1088  3.3K  [0402_CC]  30.84 122.89 180 top
R1089  0  [0402_CC]  137.78 72.21 90 bottom
R1090  0  [0402_CC]  135.87 70.56 270 bottom
R1091  10K  [0402_CC]  178.67 94.57 90 top
R1093  10K  [0402_CC]  173.84 94.57 90 top
R1094  0  [0402_CC]  172.45 95.84 0 top
R1095  0  [0402_CC]  59.8 28.65 270 bottom
R1096  0  [0402_CC]  60.94 31.45 180 bottom
R1097  2.49K  [RC0402_25]  53.45 26.62 0 top
R1099  0  [0402_CC]  49.89 28.4 270 top
R1100  4.7K  [0402_CC]  63.35 31.07 180 bottom
R1102  4.7K  [0402_CC]  63.35 29.29 180 bottom
R1103  4.7K  [0402_CC]  63.35 28.4 0 bottom
R1104  4.7K  [0402_CC]  63.35 31.96 0 bottom
R1105  4.7K  [0402_CC]  63.35 31.96 180 top
R1106  4.7K  [0402_CC]  60.43 26.75 270 bottom
R1107  4.7K  [0402_CC]  61.32 26.75 90 bottom
R1108  4.7K  [0402_CC]  52.18 29.54 0 bottom
R1109  4.7K  [0402_CC]  52.18 30.43 180 bottom
R1112  4.7K  [0402_CC]  52.94 36.78 90 top
R1113  4.7K  [0402_CC]  52.05 36.78 270 top
R1116  4.7K  [0402_CC]  52.18 33.99 180 top
R1117  4.7K  [0402_CC]  52.2 34.9 180 top
R1118  510  [RC0402_25]  44.3 20.14 270 bottom
R1119  510  [RC0402_25]  45.57 20.14 90 bottom
R1122  0  [0402_CC]  52.18 32.21 0 top
R1169  0  [0402_CC]  81.39 60.15 180 top
R1170  4.7K  [0402_CC]  83.93 36.78 270 top
R1171  4.7K  [0402_CC]  84.82 36.78 90 top
R1172  4.7K  [0402_CC]  83.93 35.13 0 top
R1173  4.7K  [0402_CC]  83.93 34.24 180 top
R1174  4.7K  [0402_CC]  95.1 29.29 180 bottom
R1175  4.7K  [0402_CC]  95.1 28.4 0 bottom
R1176  4.7K  [0402_CC]  93.07 26.88 90 bottom
R1177  4.7K  [0402_CC]  92.18 26.88 270 bottom
R1178  4.7K  [0402_CC]  83.93 30.3 180 bottom
R1179  4.7K  [0402_CC]  83.93 29.42 0 bottom
R1180  4.7K  [0402_CC]  95.1 32.84 180 bottom
R1181  4.7K  [0402_CC]  95.1 31.96 0 bottom
R1190  510  [RC0402_25]  68.31 20.02 90 bottom
R1191  510  [RC0402_25]  67.16 20.02 270 bottom
R1192  100  [0402_CC]  87.36 13.41 270 top
R1229  0  [0402_CC]  61.83 63.58 180 top
R1230  0  [0402_CC]  64.88 65.76 180 top
R1231  0  [0402_CC]  61.83 63.83 180 bottom
R1232  0  [0402_CC]  64.88 65.74 180 bottom
R1233  0  [0402_CC]  63.35 27.51 180 top
R1234  0  [0402_CC]  63.35 29.29 180 top
R1235  0  [0402_CC]  52.18 30.43 0 top
R1236  0  [0402_CC]  63.35 31.07 180 top
R1237  0  [0402_CC]  63.1 36.78 270 top
R1238  0  [0402_CC]  62.21 36.78 270 top
R1239  0  [0402_CC]  57.77 36.78 270 top
R1240  0  [0402_CC]  63.35 34.62 180 top
R1259  0  [0402_CC]  63.35 32.84 180 top
R1260  0  [0402_CC]  61.32 26.88 90 top
R1261  0  [0402_CC]  52.18 29.54 0 top
R1262  0  [0402_CC]  63.35 26.62 180 top
R1263  0  [0402_CC]  63.35 28.4 180 top
R1264  0  [0402_CC]  63.35 30.18 180 top
R1265  0  [0402_CC]  63.35 32.84 180 bottom
R1266  0  [0402_CC]  63.35 33.73 180 top
R1267  0  [0402_CC]  58.65 36.78 270 top
R1268  0  [0402_CC]  63.35 35.51 180 top
R1269  0  [0402_CC]  61.32 36.78 270 top
R1270  0  [0402_CC]  60.43 36.78 270 top
R1271  0  [0402_CC]  52.18 33.1 0 top
R1272  0  [0402_CC]  59.54 36.78 270 top
R1273  0  [0402_CC]  52.18 31.32 0 top
R1274  0  [0402_CC]  55.99 36.78 270 top
R1275  49.9  [RC0603_OV]  87.92 25.35 180 top
R1276  49.9  [RC0603_OV]  93.25 25.35 180 top
R1277  49.9  [RC0603_OV]  90.58 25.35 0 top
R1278  49.9  [RC0603_OV]  85.25 25.35 0 top
R1279  0  [0402_CC]  82.66 26.75 90 top
R1280  0  [0402_CC]  82.66 28.4 270 top
R1281  10K  [0402_CC]  88.37 36.78 90 bottom
R1282  1K  [0402_CC]  86.59 36.78 270 top
R1283  1.5K  [0402_CC]  85.71 36.78 270 top
R1284  0  [0402_CC]  91.55 28.65 270 bottom
R1285  0  [0402_CC]  92.69 31.45 180 bottom
R1286  2.49K  [RC0402_25]  85.2 26.62 0 top
R1287  4.7K  [0402_CC]  95.1 31.07 180 bottom
R1288  0  [0402_CC]  87.48 36.78 270 top
R1289  0  [0402_CC]  83.93 32.46 0 top
R1290  0  [0402_CC]  95.1 27.51 180 top
R1291  0  [0402_CC]  95.1 28.4 180 top
R1292  0  [0402_CC]  83.93 30.43 0 top
R1293  0  [0402_CC]  95.1 33.73 180 top
R1294  0  [0402_CC]  89.52 36.78 270 top
R1295  0  [0402_CC]  95.1 36.4 180 top
R1296  0  [0402_CC]  93.07 36.78 270 top
R1297  0  [0402_CC]  95.1 32.84 180 top
R1298  0  [0402_CC]  93.07 26.88 90 top
R1299  0  [0402_CC]  83.93 29.54 0 top
R1300  0  [0402_CC]  95.1 26.62 180 top
R1301  0  [0402_CC]  95.1 31.07 180 top
R1302  0  [0402_CC]  95.1 29.29 180 top
R1303  0  [0402_CC]  95.1 31.96 180 top
R1304  0  [0402_CC]  95.1 34.62 180 top
R1305  0  [0402_CC]  90.4 36.78 270 top
R1306  0  [0402_CC]  93.96 36.78 270 top
R1307  0  [0402_CC]  95.1 35.51 180 top
R1308  0  [0402_CC]  92.18 36.78 270 top
R1309  0  [0402_CC]  83.93 33.35 0 top
R1310  0  [0402_CC]  91.29 36.78 270 top
R1311  0  [0402_CC]  83.93 31.32 0 top
R1312  0  [0402_CC]  88.37 36.78 270 top
R1313  0  [0402_CC]  95.1 30.18 180 top
R1314  1.00k  [0402_CC]  51.8 108.28 270 top
R1315  1.00k  [0402_CC]  53.07 108.28 270 top
R1316  1.00k  [0402_CC]  54.34 108.28 270 top
R1319  10K  [0402_CC]  114.66 102.69 90 top
R1320  10K  [0402_CC]  64.5 108.79 270 top
R1321  0  [0402_CC]  62.59 108.79 270 top
R1322  0  [0402_CC]  62.85 100.66 90 top
R1323  4.7K  [0402_CC]  63.86 100.66 90 top
R1324  4.7K  [0402_CC]  63.48 108.79 270 top
R1325  100  [0402_CC]  189.34 68.2 180 top
R1326  100  [0402_CC]  188.88 84.41 180 top
R1327  100  [0402_CC]  48.24 132.92 270 top
R1328  0  [0402_CC]  102.6 90.88 90 top
R1329  0  [0402_CC]  71.48 57.48 180 bottom
R1330  0  [0402_CC]  71.48 58.37 180 bottom
R1331  0  [0402_CC]  47.99 22.94 0 top
R1332  0  [0402_CC]  47.99 23.95 0 top
R1333  0  [0402_CC]  79.74 22.94 0 top
R1334  0  [0402_CC]  79.74 23.95 0 top
R1338  75k  [RC0402_25]  123.02 60.91 90 top
R1339  10K  [0402_CC]  117.41 61.67 0 top
R1340  0  [0402_CC]  117.41 60.66 0 top
R1342  0  [0402_CC]  80.24 90.5 180 bottom
R1343  0  [0402_CC]  68.18 93.04 0 bottom
R1344  0  [0402_CC]  97.77 90.88 90 bottom
R1900  0  [0402_CC]  99.93 38.56 90 top
R2090  100K  [0402_CC]  99.42 40.85 0 top
R2098  100K  [0402_CC]  30.46 43.64 0 top
R2099  100K  [0402_CC]  30.46 41.61 0 top
R2100  100K  [0402_CC]  30.46 38.69 0 top
R2101  100K  [0402_CC]  41.64 37.8 180 top
R2102  100K  [0402_CC]  41.64 39.58 180 top
R2103  100K  [0402_CC]  33.38 31.07 180 top
R2104  100K  [0402_CC]  41.64 41.35 180 top
R2107  10K  [0402_CC]  57.64 106.38 180 bottom
R2109  10K  [0402_CC]  53.83 106.38 180 bottom
R2111  10K  [0402_CC]  50.02 106.38 180 bottom
R2113  1.5K  [0402_CC]  101.07 36.4 0 top
R2114  0  [0402_CC]  76.87 76.66 0 bottom
R2115  0  [0402_CC]  78.37 76.15 0 bottom
R2116  0  [0402_CC]  72.75 76.66 180 bottom
R2117  0  [0402_CC]  74.91 76.15 180 bottom
R2118  0  [0402_CC]  76.87 75.64 0 bottom
R2119  0  [0402_CC]  78.37 75.14 0 bottom
R2120  0  [0402_CC]  72.75 75.64 180 bottom
R2121  0  [0402_CC]  74.91 75.14 180 bottom
R2122  0  [0402_CC]  76.87 74.63 0 bottom
R2123  0  [0402_CC]  78.37 74.12 0 bottom
R2124  0  [0402_CC]  72.75 74.63 180 bottom
R2125  0  [0402_CC]  74.91 74.12 180 bottom
R2126  0  [0402_CC]  76.87 73.61 0 bottom
R2127  0  [0402_CC]  78.37 73.1 0 bottom
R2128  0  [0402_CC]  72.75 73.61 180 bottom
R2129  0  [0402_CC]  74.91 73.1 180 bottom
R2130  0  [0402_CC]  78.37 77.17 0 bottom
R2131  0  [0402_CC]  78.37 72.09 0 bottom
R2132  0  [0402_CC]  74.91 77.17 180 bottom
R2133  0  [0402_CC]  74.91 72.09 180 bottom
R2134  0  [0402_CC]  84.94 115.14 0 top
R2135  0  [0402_CC]  87.99 124.16 0 bottom
R2136  2.2K  [RC0402_25]  84.94 117.55 180 top
R2137  0  [0402_CC]  93.83 124.41 90 top
R2138  0  [0402_CC]  94.47 112.35 270 top
R2139  0  [0402_CC]  94.47 108.03 270 top
R2140  0  [0402_CC]  93.07 122 180 top
R2141  0  [0402_CC]  85.83 106.63 180 top
R2142  0  [0402_CC]  85.83 112.85 180 top
R2143  0  [0402_CC]  85.83 105.62 180 top
R2144  0  [0402_CC]  85.83 111.84 180 top
R2145  0  [0402_CC]  93.07 115.27 0 top
R2146  10K  [RC0402_25]  93.07 116.28 0 top
R2147  0  [0402_CC]  101.45 129.87 0 top
R2148  10K  [RC0402_25]  84.56 120.47 180 bottom
R2149  10K  [RC0402_25]  87.74 120.47 0 bottom
R2150  20  [RC0402_25]  83.04 120.98 90 top
R2151  20  [RC0402_25]  82.96 118.95 270 top
R2152  0  [0402_CC]  82.28 92.66 90 bottom
R2153  0  [0402_CC]  68.18 94.31 0 bottom
R2154  100K  [0402_CC]  59.67 108.79 90 top
R2155  0  [0402_CC]  80.24 91.77 180 bottom
R2156  0  [0402_CC]  103.36 107.52 90 bottom
R2157  0  [0402_CC]  117.2 79.58 0 bottom
R2158  0  [0402_CC]  134.6 61.8 90 top
R2159  0  [0402_CC]  130.79 61.8 90 top
R2160  0  [0402_CC]  129.39 63.96 90 top
R2161  0  [0402_CC]  99.49 69.64 90 bottom
R2166  100  [0402_CC]  167.87 121.87 180 top
R2168  100  [0402_CC]  167.87 122.76 180 top
R2169  100  [0402_CC]  167.87 129.24 180 top
R2576  0  [RC0402_25]  114.53 15.06 90 top
R2579  0  [RC0402_25]  127.62 15.06 90 top
R2584  0  [RC0805_OV]  131.93 4.02 180 bottom
R2585  47K  [RC0402_25]  128.63 15.06 90 top
R2586  0  [RC0402_25]  129.65 15.06 90 top
R2587  0  [RC0402_25]  130.92 15.06 90 top
R2592  0  [RC0402_25]  124.57 15.06 90 top
R2593  0  [RC0402_25]  125.58 15.06 90 top
R2594  0  [0402_CC]  78.97 55.96 180 bottom
R2595  0  [0402_CC]  77.2 57.36 90 top
R2596  0  [0402_CC]  78.97 55.96 180 top
R2597  0  [0402_CC]  78.97 56.97 0 bottom
R2603  0  [0402_CC]  64.75 38.43 0 top
R2604  0  [0402_CC]  66.66 27.64 0 top
R2605  0  [0402_CC]  66.66 29.42 0 top
R2606  0  [0402_CC]  49.51 32.34 180 top
R2607  0  [0402_CC]  49.51 31.19 180 top
R2608  0  [0402_CC]  97.26 36.4 0 top
R2609  0  [0402_CC]  93.07 39.07 90 top
R2610  0  [0402_CC]  90.02 39.07 90 top
R2611  0  [0402_CC]  97.26 34.11 0 top
R2612  0  [0402_CC]  98.15 27.51 0 top
R2613  0  [0402_CC]  98.15 28.78 0 top
R2614  0  [0402_CC]  82.4 32.46 180 top
R2615  0  [0402_CC]  81.77 30.69 180 top
R2616  0  [RC0402_25]  112.5 15.06 90 top
R2617  0  [RC0402_25]  113.52 15.06 90 top
R2618  0  [RC0402_25]  122.54 15.06 90 top
R2619  0  [RC0402_25]  123.55 15.06 90 top
R2620  0  [0402_CC]  64.75 39.32 0 top
R2635  100  [0402_CC]  167.87 120.98 180 top
R2639  0  [0402_CC]  131.43 103.08 90 top
R2640  0  [0402_CC]  121.39 117.68 90 top
R2641  0  [0402_CC]  99.93 92.53 90 top
R2642  0  [0402_CC]  103.99 90.88 90 bottom
R2643  0  [0402_CC]  130.54 103.08 90 top
R2644  0  [0402_CC]  121.39 115.39 270 top
R2684  10K  [0402_CC]  121.65 116.16 180 bottom
R2694  4.7K  [0402_CC]  131.68 106.63 180 bottom
R2695  4.7K  [0402_CC]  25.25 77.93 270 top
R2696  10K  [0402_CC]  22.71 75.39 270 top
R2697  4.7K  [0402_CC]  38.84 89.49 0 top
SW1  EG2209A  [SW6_DPDT_11X6MM]  4.17 25.99 90 top
SW2  430152050826  [SW4_PB_6P2SQ_SM]  34.27 3.89 180 top
SW3  430152050826  [SW4_PB_6P2SQ_SM]  4.93 41.1 90 top
SW4  430152050826  [SW4_PB_6P2SQ_SM]  21.44 3.89 180 top
SW5  416131160804  [SW4_DIP_1P27_6P3X5P7]  52.43 102.44 0 top
SW6  TL1015AF160QG  [SW2_SPST_4X3_SM_F]  3.16 105.36 90 top
SW7  430152050826  [SW4_PB_6P2SQ_SM]  120 21.03 180 top
SW8  430152050826  [SW4_PB_6P2SQ_SM]  54.64 113.41 0 top
T1  TTWB1010L  [XFMR6_6P6X6P2]  138.79 17.22 90 top
T2  TTWB1010L  [XFMR6_6P6X6P2]  153.02 17.22 90 top
TP1  TP_35MIL  [TESTPOINT_35MIL]  22.97 33.73 180 top
TP2  TP_35MIL  [TESTPOINT_35MIL]  24.24 28.15 90 top
TP3  5006  [TP_TH_063]  12.68 4.65 0 top
TP4  5006  [TP_TH_063]  178.16 14.05 90 top
TP5  5006  [TP_TH_063]  159.62 136.1 0 top
TP6  5006  [TP_TH_063]  3.41 127.21 0 top
TP7  TP_35MIL  [TESTPOINT_35MIL]  135.36 95.58 90 top
TP8  TP_35MIL  [TESTPOINT_35MIL]  100.56 57.23 0 top
TP9  TP_35MIL  [TESTPOINT_35MIL]  116.06 72.98 0 top
TP10  TP_35MIL  [TESTPOINT_35MIL]  106.91 57.48 0 top
TP11  TP_35MIL  [TESTPOINT_35MIL]  107.42 58.88 0 top
TP12  TP_35MIL  [TESTPOINT_35MIL]  115.55 76.91 0 top
TP13  TP_35MIL  [TESTPOINT_35MIL]  96.5 51.51 0 top
TP14  TP_35MIL  [TESTPOINT_35MIL]  80.37 63.07 0 top
TP15  TP_35MIL  [TESTPOINT_35MIL]  83.34 59.74 0 top
TP16  TP_35MIL  [TESTPOINT_35MIL]  142.35 59.9 0 top
TP17  TP_35MIL  [TESTPOINT_35MIL]  136.89 64.72 0 top
TP18  TP_35MIL  [TESTPOINT_35MIL]  123.93 69.04 0 top
TP24  TP_35MIL  [TESTPOINT_35MIL]  134.35 112.09 0 top
TP25  TP_35MIL  [TESTPOINT_35MIL]  28.56 69.17 90 top
TP26  TP_35MIL  [TESTPOINT_35MIL]  30.59 93.68 90 top
TP41  TP_35MIL  [TESTPOINT_35MIL]  131.43 72.47 180 top
TP42  TEST POINT  [TP_TH_018]  171.3 17.35 270 top
TP43  TEST POINT  [TP_TH_018]  169.27 17.35 270 top
TP44  TEST POINT  [TP_TH_018]  167.24 17.35 270 top
TP45  -  [TPAD_030]  33.1 119.89 270 top
TP46  -  [TPAD_030]  33.46 118.6 270 top
TP47  -  [TPAD_030]  26.27 109.43 270 top
TP48  -  [TPAD_030]  29.7 108.16 270 top
TP50  -  [TPAD_050]  172.95 106.5 90 top
TP51  -  [TPAD_020]  112.12 3 0 top
TP53  TP_35MIL  [TESTPOINT_35MIL]  31.22 121.36 270 top
TP54  TP_35MIL  [TESTPOINT_35MIL]  27.92 123.4 270 top
TP55  TP_35MIL  [TESTPOINT_35MIL]  25.25 123.4 0 top
TP56  TP_35MIL  [TESTPOINT_35MIL]  29.57 121.36 270 top
TP57  TP_35MIL  [TESTPOINT_35MIL]  31.1 110.49 270 top
TP58  TP_35MIL  [TESTPOINT_35MIL]  29.7 111.08 270 top
TP59  TP_35MIL  [TESTPOINT_35MIL]  29.7 109.68 270 top
TP60  TP_35MIL  [TESTPOINT_35MIL]  27.54 110.57 270 top
TP61  TP_35MIL  [TESTPOINT_35MIL]  27.54 107.52 270 top
TP62  TP_35MIL  [TESTPOINT_35MIL]  25.25 122 270 top
TP63  TP_35MIL  [TESTPOINT_35MIL]  122.41 108.28 0 top
TP64  TP_35MIL  [TESTPOINT_35MIL]  121.01 108.28 0 top
TP65  TP_35MIL  [TESTPOINT_35MIL]  118.85 109.93 0 top
TP66  TP_35MIL  [TESTPOINT_35MIL]  118.85 111.33 0 top
TP67  -  [TPAD_030]  105.01 101.68 0 top
TP68  -  [TPAD_030]  102.98 101.68 0 top
TP69  -  [TPAD_030]  111.11 99.65 0 top
TP70  -  [TPAD_030]  111.11 101.68 0 top
TP71  -  [TPAD_030]  109.07 101.68 0 top
TP72  -  [TPAD_030]  107.04 101.68 0 top
TP73  -  [TPAD_030]  107.04 99.65 0 top
TP74  -  [TPAD_030]  105.01 99.65 0 top
TP75  -  [TPAD_030]  109.07 99.65 0 top
TP76  -  [TPAD_030]  102.98 99.65 0 top
TP77  TP_35MIL  [TESTPOINT_35MIL]  59.54 118.95 0 top
TP78  TP_35MIL  [TESTPOINT_35MIL]  58.15 118.82 0 top
TP94  TP_35MIL  [TESTPOINT_35MIL]  109.84 82.76 0 top
TP95  TP_35MIL  [TESTPOINT_35MIL]  113.77 82.63 0 top
TP96  TP_35MIL  [TESTPOINT_35MIL]  87.48 87.58 0 top
TP97  TP_35MIL  [TESTPOINT_35MIL]  85.83 87.58 0 top
TP98  TP_35MIL  [TESTPOINT_35MIL]  85.07 88.85 0 top
TP99  TP_35MIL  [TESTPOINT_35MIL]  84.18 87.58 0 top
TP100  TP_35MIL  [TESTPOINT_35MIL]  88.25 88.85 0 top
TP101  TP_35MIL  [TESTPOINT_35MIL]  86.59 88.85 0 top
TP102  -  [TPAD_030]  99.8 113.49 0 top
TP103  -  [TPAD_030]  99.8 111.71 0 top
TP1022  TP_35MIL  [TESTPOINT_35MIL]  95.1 116.16 90 top
TP1023  TP_35MIL  [TESTPOINT_35MIL]  93.58 117.68 90 top
TP1024  TP_35MIL  [TESTPOINT_35MIL]  82.66 116.28 90 top
TP1025  TP_35MIL  [TESTPOINT_35MIL]  89.39 125.68 90 top
TP1026  TP_35MIL  [TESTPOINT_35MIL]  92.31 125.68 90 top
TP1027  TP_35MIL  [TESTPOINT_35MIL]  95.1 117.68 90 top
TP1028  TP_35MIL  [TESTPOINT_35MIL]  90.79 125.68 90 top
TP1029  TP_35MIL  [TESTPOINT_35MIL]  90.79 124.16 90 top
TP1030  TP_35MIL  [TESTPOINT_35MIL]  92.31 124.16 90 top
TP1031  TP_35MIL  [TESTPOINT_35MIL]  96.63 116.16 90 top
TP1055  -  [TPAD_020]  111.23 14.56 0 top
TP1056  -  [TPAD_020]  117.2 1.98 0 top
TP1057  -  [TPAD_020]  118.47 1.98 0 top
TP1058  -  [TPAD_020]  119.74 1.98 0 top
TP1059  -  [TPAD_020]  121.01 1.98 0 top
TP1060  -  [TPAD_020]  123.55 2.87 0 top
TP1061  -  [TPAD_020]  127.36 1.98 0 top
TP1062  -  [TPAD_020]  128.63 1.98 0 top
TP1063  -  [TPAD_020]  130.28 1.98 0 top
TP1064  -  [TPAD_020]  130.28 16.72 0 top
TP1065  TP_35MIL  [TESTPOINT_35MIL]  56.24 66.88 0 top
TP1066  TP_35MIL  [TESTPOINT_35MIL]  72.85 86.13 0 top
TP1067  TP_35MIL  [TESTPOINT_35MIL]  60.14 65.29 0 top
TP1068  TP_35MIL  [TESTPOINT_35MIL]  65.77 17.73 0 top
TP1069  TP_35MIL  [TESTPOINT_35MIL]  65.77 15.83 0 top
TP1070  TP_35MIL  [TESTPOINT_35MIL]  89.01 16.21 0 top
TP1071  TP_35MIL  [TESTPOINT_35MIL]  89.01 14.68 0 top
TVS1  ESD5B5.0ST1G  [DIODE2_SOD523]  24.47 19 0 top
U1  MP2143DJ  [TSOT23_8_0P65_2X1]  23.22 30.81 180 top
U2  UM805RE  [SOT_143]  13.19 30.05 0 top
U3  UM1750S-00  [SOT23-5_A]  108.41 39.35 90 top
U4  AMS1117-1.8  [SOT223]  125.71 50.12 0 top
